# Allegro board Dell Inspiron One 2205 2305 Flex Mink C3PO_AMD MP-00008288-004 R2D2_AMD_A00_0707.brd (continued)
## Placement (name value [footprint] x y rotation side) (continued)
CN28  HEADER1X6PK6  [DH5_200P1X6_K6]  55.43 69.57 90 top
CN29  HEADER3PK3  [DH2_200P1X3_K3]  59.95 30.73 270 top
CN30  HEADER6PK5  [DH5_200P1X6_K5]  75.45 40.51 0 top
CN31  WFR8P  [DBH8_200P2X4_1000X505N]  167.65 62.61 270 top
CN32  WFR1X4P  [DBH4_200P1X4_1000X450]  172.73 62.61 270 top
CN33  WFR1X4P  [DWAF4_254P575W1006L]  169.43 241.55 0 top
CN34  WFR1X4P  [DCON_FAN_4_KORTAK]  180.86 241.17 0 top
CN35  WFR1X4P  [DCON_FAN_4_KORTAK]  190 242.44 90 top
D1  BAT54HT1G  [SOD323]  184.29 249.56 90 top
D2  BAT54HT1G  [SOD323]  188.35 252.22 0 top
D3  BAT54HT1G  [SOD323]  167.02 248.79 0 top
D4  BAT54HT1G  [SOD323]  142.76 220.6 90 top
D5  BAT54HT1G  [SOD323]  114.06 212.85 90 top
D6  BAT54HT1G  [SOD323]  93.36 207.9 0 top
D7  BAT54HT1G  [SOD323]  34.62 104.97 0 top
D8  BAT54C  [SOT23_3P_AKA]  140.85 87.25 180 top
D9  BAT54HT1G  [SOD323]  133.23 91.57 90 top
D10  BAT54C  [SOT23_3P_AKA]  158.51 77.34 270 top
D11  BAT54C  [SOT23_3P_AKA]  164.35 76.58 270 top
D12  BAT54C  [SOT23_3P_AKA]  180.1 64.14 180 top
D13  1SMA18A  [SMA]  137.81 13.46 180 top
D14  AOZ8212  [SOT23_3P]  13.85 65.28 90 bottom
D15  AOZ8212  [SOT23_3P]  13.85 49.28 90 bottom
D16  AOZ8212  [SOT23_3P]  109.38 14.3 270 bottom
D17  CPDU5V0U  [D0603_AC]  179.46 63.37 270 bottom
D18  CPDU12V0U  [D0603_AC]  147.2 57.78 180 top
EC1  220UF  [SEC630D600H]  22.11 114.3 90 top
EC2  470UF  [DEC063D110H]  60.08 47.05 270 top
EC11  100UF  [TC734331D]  150.25 61.21 180 top
F2  RESETTABLE1A5  [SF1206]  74.94 12.57 270 top
F3  RESETTABLE1A5  [SF1206]  46.49 10.41 0 top
F4  RESETTABLE1A5  [SF1206]  13.73 71.75 90 bottom
H1  OTHER_FMARK  [FM_A]  13.73 251.08 0 top
H2  OTHER_FMARK  [FM_A]  191.78 250.19 0 top
H3  OTHER_FMARK  [FM_A]  189.75 4.32 0 top
H4  OTHER_FMARK  [FM_A]  13.73 251.08 180 bottom
H5  OTHER_FMARK  [FM_A]  191.78 250.19 180 bottom
H6  OTHER_FMARK  [FM_A]  189.75 4.32 180 bottom
J1  DIMM240P  [SLT_DDR3-240_LOTES_WHT]  172.76 219.61 270 top
J2  DIMM240P  [SLT_DDR3-240_LOTES_WHT]  181.76 219.61 270 top
J3  HEADER2X13PK25  [SCON_HAD-VERTICAL_25P_K25]  125.36 84.58 180 top
J4  B2B-2X3P  [DH6_200P2X3N]  141.74 80.01 0 top
J6  B2B2X5K10  [DH9_254P2X5N_K10]  153.65 3.05 0 top
L1  80R  [L0805]  100.94 228.85 0 top
L2  30R  [L0603]  138.57 230.89 0 top
L3  80R  [L0805]  128.53 223.39 0 top
L4  150NH  [CKS750L700W520H]  109.48 217.81 90 top
L5  1UH  [CKS1150L1000W500H]  120.66 207.9 270 top
L6  0.36UH  [CKS1000L1000W400H]  104.02 183.64 270 top
L8  220R  [L0402]  63.64 170.69 0 top
L9  220R  [L0402]  57.92 170.18 270 top
L10  0.36UH  [CKS1000L1000W400H]  91.26 183.45 270 top
L11  220R  [L0603]  66.18 170.69 0 top
L13  220R  [L0402]  60.77 169.14 0 top
L14  100R  [L0603]  16.2 130.62 0 top
L15  220R  [L0603]  59.42 127.56 0 top
L16  600R  [L0603]  20 125.13 90 top
L17  600R  [L0603]  38.05 102.3 180 top
L18  600R  [L0603]  40.65 97.35 270 top
L19  600R  [L0603]  32.84 96.84 0 top
L20  60R  [L1806]  82.75 86.3 180 top
L21  60R  [L1806]  99.32 86.74 270 top
L22  60R  [L1806]  121.36 68.96 180 top
L23  220R  [L0603]  75.58 73.66 0 top
L24  220R  [L0603]  74.94 60.96 0 top
L25  70R  [L0402]  27.06 58.1 0 top
L26  30R  [L0603]  30.36 58.04 0 top
L27  30R  [L0603]  19.7 56.07 0 top
L28  120R  [L1206]  183.78 47.37 0 top
L29  30R  [L0603]  27.7 55.12 0 top
L30  30R  [L0603]  21.22 45.21 0 top
L31  70R  [L0402]  27.7 46.86 0 top
L32  70R  [L0402]  23.44 27.43 270 top
L33  60R  [L0805]  64.65 24.51 90 top
L34  120R  [L0805]  159.27 11.43 180 top
L35  70R  [L0402]  20.08 16.38 270 top
L36  90R  [CMC-2012_CHILISIN]  60.34 18.03 90 top
L37  90R  [CMC-2012_CHILISIN]  63.38 18.03 90 top
L38  90R  [CMC-2012_CHILISIN]  85.35 18.03 90 top
L39  90R  [CMC-2012_CHILISIN]  88.47 18.03 90 top
L40  30R  [L0603]  74.43 9.02 270 top
L41  120R  [L0805]  159.27 13.53 180 top
L42  30R  [L0603]  48.52 8 0 top
L43  220R  [L0402]  66.3 172.97 270 bottom
L44  220R  [L0402]  62.49 172.97 270 bottom
L45  220R  [L0402]  61.48 172.97 270 bottom
L46  220R  [L0402]  54.21 164.74 270 bottom
L47  30R  [L0603]  15 74.93 0 bottom
L50  600R  [L0603]  36.4 108.78 270 bottom
L51  90R  [CMC-2012_CHILISIN]  19.81 94.09 0 bottom
L52  90R  [CMC-2012_CHILISIN]  18.55 88.19 270 bottom
L53  220R  [L0402]  91.32 84.45 270 bottom
L55  220R  [L0402]  96.91 78.89 270 bottom
L56  220R  [L0402]  95.9 78.93 90 bottom
L57  220R  [L0402]  104.02 78.55 90 bottom
L58  220R  [L0603]  85.61 73.28 180 bottom
L59  220R  [L0402]  17.41 66.42 90 bottom
L60  70R  [L0402]  11.44 72.64 90 bottom
L61  220R  [L0402]  13.85 61.98 180 bottom
L62  220R  [L0402]  110.31 62.87 90 bottom
L63  220R  [L0402]  13.98 52.2 270 bottom
L64  220R  [L0402]  77.61 54.86 0 bottom
L65  220R  [L0402]  14.11 46.48 90 bottom
L66  2.2UH  [CKS290L250W210H]  133.49 38.23 0 bottom
L67  120R  [L0603]  15.38 39.05 270 bottom
L68  120R  [L0603]  124.85 40.01 0 bottom
L69  600R  [L0603]  54.85 37.08 270 bottom
L70  600R  [L0603]  52.84 31.11 90 bottom
L71  600R  [L0603]  147.01 21.02 270 bottom
L72  600R  [L0603]  145.43 20.76 270 bottom
L73  600R  [L0603]  143.9 20.76 270 bottom
L74  220R  [L0402]  106.49 15.21 0 bottom
L75  600R  [L0603]  141.49 19.18 90 bottom
L76  600R  [L0603]  139.96 19.18 90 bottom
L77  600R  [L0603]  138.44 19.18 90 bottom
L78  600R  [L0603]  136.92 19.18 90 bottom
L79  600R  [L0603]  135.39 18.92 90 bottom
L80  220R  [L0402]  106.49 13.39 0 bottom
L82  80R  [L0805]  179.34 66.78 0 bottom
LED1  LED_GRN  [LED0603_BRIGHT]  18.68 136.78 90 top
LED2  LED_YEL  [LED0603]  44.84 51.18 180 top
LED3  LED_WHT  [LED2_254P460L880W074H]  8.15 26.72 90 bottom
M1  OTHER_STANDOFF  [OTHER_SMT213]  154.02 185.1 0 top
M2  OTHER_STANDOFF  [OTHER_SMT213]  66.94 177.8 0 top
M3  OTHER_STANDOFF  [OTHER_SMT213]  66.94 126.36 0 top
M4  OTHER_STANDOFF  [OTHER_SMT213]  87.98 119.06 0 top
M5  OTHER_INSERT  [HOLE_STEEL-INSERT]  25.97 107.17 0 top
M6  OTHER_INSERT  [HOLE_STEEL-INSERT]  50.17 107.17 0 top
M7  OTHER_INSERT  [HOLE_STEEL-INSERT]  24.42 66.2 0 top
M8  OTHER_INSERT  [HOLE_STEEL-INSERT]  48.62 66.2 0 top
MH1  OTHER_M-HOLE  [HOLE_3-7_8MM_BOT14]  177.55 249 0 top
MH2  OTHER_M-HOLE  [HOLE_3-7_8MM_BOT14]  31.8 249 0 top
MH3  OTHER_M-HOLE  [HOLE_4-1_8MM_BOT14]  106.25 249 0 top
MH4  OTHER_M-HOLE  [HOLE_3-7_8MM_BOT14]  158.18 244.01 0 top
MH5  OTHER_M-HOLE  [HOLE_3-7_8MM_BOT14]  102 206.91 0 top
MH6  OTHER_M-HOLE  [HOLE_3-7_8MM_BOT14]  31.8 72.32 0 top
MH7  OTHER_M-HOLE  [HOLE_3-7_8MM_BOT14]  177.55 72.32 0 top
MH8  OTHER_M-HOLE  [HOLE_4-1_8MM_BOT14]  106.25 23.7 0 top
MH9  OTHER_M-HOLE  [HOLE_3-7_8MM_BOT14]  31.8 4 0 top
MH10  OTHER_M-HOLE  [HOLE_3-7_8MM_BOT14]  177.55 4 0 top
NOREF  -  [unnamed]  85.2 122.94 0 top
NOREF#2  -  [unnamed]  112.91 47.62 0 top
NOREF#3  -  [#2]  0.9 -20.32 0 top
NOREF#4  -  [unnamed]  45.86 136.4 0 top
NOREF#5  -  [unnamed]  72.27 83.12 0 top
NOREF#6  -  [unnamed]  76.34 167.13 0 top
NOREF#7  -  [unnamed]  134.44 214.44 0 top
NOREF#8  -  [#2]  65.73 240.92 180 bottom
PC1  4.7UF  [C0805]  107.96 243.14 180 top
PC2  150PF  [C0603]  126.1 237.4 90 top
PC3  10PF  [C0402]  154.32 237.49 0 top
PC4  1500PF  [C0603]  107.78 236.62 180 top
PC5  100PF  [C0402]  149.58 232.28 90 top
PC6  10UF  [C0805]  160.03 235.97 0 top
PC7  0.1UF  [C0402]  115.9 245.36 270 top
PC8  2200PF  [C0603]  128.59 238.37 180 top
PC9  0.1UF  [C0402]  119.76 245.25 270 top
PC10  2200PF  [C0603]  106.76 238.96 90 top
PC11  100PF  [C0603]  108.54 238.96 90 top
PC12  10UF  [C0805]  160.03 233.93 0 top
PC13  10UF  [C0805]  160.03 231.65 0 top
PC14  0.22UF  [C0603]  117.76 230.73 180 top
PC15  0.22UF  [C0603]  114.93 230.72 180 top
PC16  0.1UF  [C0603]  107.88 227.34 180 top
PC17  10UF  [C1206]  96.53 229.62 180 top
PC18  0.033UF  [C0603]  152.92 235.46 270 top
PC19  0.1UF  [C0603]  160.03 229.62 0 top
PC20  0.1UF  [C0603]  96.15 225.43 180 top
PC21  10UF  [C1206]  96.53 227.33 180 top
PC22  560UF  [DEC063D60H]  189.24 222.76 270 top
PC23  10UF  [C1206]  123.33 224.92 180 top
PC24  1UF  [C0603]  138.38 225.55 0 top
PC25  0.1UF  [C0603]  170.33 231.26 270 top
PC26  0.22UF  [C0603]  122.81 230.01 270 top
PC27  0.1UF  [C0603]  122.76 222.69 180 top
PC28  22UF  [C1210]  165.24 231.27 270 top
PC29  10UF  [C1206]  168.17 231.24 270 top
PC30  1UF  [C0603]  154.57 221.74 180 top
PC31  1UF  [C0603]  145.27 221.89 0 top
PC32  560UF  [DEC063D60H]  189.24 216.28 270 top
PC33  1UF  [C0603]  153.55 224.16 270 top
PC34  1UF  [C0603]  114.69 216.03 0 top
PC35  1UF  [C0603]  108.66 208.91 90 top
PC36  1UF  [C0603]  84.72 208.89 90 top
PC37  1UF  [C0603]  94.5 209.8 0 top
PC38  10UF  [C1206]  92.72 201.23 180 top
PC39  10UF  [C1206]  106.18 200.53 180 top
PC40  1500PF  [C0603]  92.4 199.01 180 top
PC41  0.1UF  [C0603]  105.87 198.37 180 top
PC42  22UF  [C0805]  114.95 192.53 180 top
PC43  0.1UF  [C0603]  114.5 188.72 180 top
PC44  560UF  [DEC063D60H]  121.8 197.87 270 top
PC45  560UF  [DEC063D60H]  115.44 197.04 270 top
PC46  22UF  [C0805]  114.95 190.5 180 top
PC47  560UF  [DEC063D60H]  82.81 178.56 0 top
PC48  560UF  [DEC063D60H]  93.36 174.24 0 top
PC49  560UF  [DEC063D60H]  86.88 173.48 0 top
PC50  560UF  [DEC063D60H]  90.82 168.28 0 top
PC51  560UF  [DEC063D60H]  83.7 167.51 0 top
PC52  0.1UF  [C0603]  189.49 165.23 180 top
PC53  560UF  [DEC063D60H]  189.24 157.99 270 top
PC54  560UF  [DEC063D60H]  189.24 151.51 270 top
PC55  0.1UF  [C0603]  73.52 133.07 90 top
PC56  560UF  [DEC063D60H]  77.58 132.26 0 top
PC57  0.1UF  [C0603]  70.37 123.06 0 top
PC58  1500PF  [C0603]  80.17 115.8 180 top
PC59  10UF  [C1206]  77.23 102.87 180 top
PC60  0.1UF  [C0603]  86.98 109.04 180 top
PC61  560UF  [DEC063D60H]  60.84 119.38 270 top
PC62  10UF  [C1206]  78.37 105.16 180 top
PC63  0.1UF  [C0603]  96.86 110.39 0 top
PC64  33PF  [C0402]  104.4 108.97 0 top
PC65  22UF  [C1210]  85.84 113.13 270 top
PC66  22UF  [C1210]  89.34 113.08 270 top
PC67  33PF  [C0402]  92.29 107.26 0 top
PC68  0.1UF  [C0603]  96.2 103.68 180 top
PC69  0.1UF  [C0603]  85.61 102.36 180 top
PC70  0.1UF  [C0603]  27.89 61.72 90 top
PC71  22UF  [C1206]  134.88 53.59 90 top
PC72  22UF  [C1206]  137.55 53.59 90 top
PC73  330UF  [TC734328D]  173.24 49.28 0 top
PC74  330UF  [TC734328D]  158 48.01 180 top
PC75  0.1UF  [C0603]  185.94 38.48 90 top
PC76  10UF  [C1206]  147.46 41.4 270 top
PC77  10UF  [C1206]  149.74 41.4 270 top
PC78  330UF  [SEC630D580H]  171.71 37.85 0 top
PC79  0.1UF  [C0603]  145.48 36.2 270 top
PC80  2200PF  [C0603]  138.95 33.66 180 top
PC81  0.01UF  [C0603]  141.62 33.15 270 top
PC82  10UF  [C1206]  174.13 26.42 90 top
PC83  0.1UF  [C0603]  153.05 30.61 180 top
PC84  330UF  [SEC630D580H]  152.54 26.54 0 top
PC85  330UF  [SEC630D580H]  181.62 40.26 270 top
PC86  1500PF  [C0603]  174.25 29.72 180 top
PC87  330UF  [SEC630D580H]  152.54 34.67 0 top
PC88  22UF  [C1210]  171.21 32.51 180 top
PC89  1000PF  [C0603]  163.9 20.83 0 top
PC90  0.1UF  [C0603]  167.02 16.89 90 top
PC91  4.7UF  [C0603]  168.92 16.89 90 top
PC92  220UF  [TC734318D]  67.96 24.38 90 top
PC93  0.1UF  [C0402]  175.65 10.41 0 top
PC94  1500PF  [C0603]  186.19 13.59 0 top
PC95  0.1UF  [C0603]  170.7 16.76 270 top
PC96  10UF  [C1206]  178.83 17.14 270 top
PC97  22UF  [C1210]  175.78 17.02 270 top
PC98  0.1UF  [C0402]  163.97 7.56 180 top
PC99  1UF  [C0603]  165.94 5.59 270 top
PC100  1UF  [C0603]  167.52 5.59 270 top
PC101  1500PF  [C0603]  128.59 238.37 180 bottom
PC102  0.1UF  [C0603]  119.33 233.68 180 bottom
PC103  10UF  [C0805]  160.06 236.12 0 bottom
PC104  10UF  [C0805]  160.06 233.93 0 bottom
PC105  22UF  [C1210]  123.2 223.01 180 bottom
PC106  2200PF  [C0603]  173.11 227.58 180 bottom
PC107  4700PF  [C0603]  119.64 220.85 90 bottom
PC108  10UF  [C1206]  123.24 226.01 180 bottom
PC109  1500PF  [C0603]  174.51 231.14 270 bottom
PC110  22UF  [C1210]  123.2 219.46 180 bottom
PC111  10UF  [C1206]  172.35 231.14 270 bottom
PC112  22UF  [C1210]  169.3 231.14 270 bottom
PC113  1500PF  [C0603]  123.07 216.79 180 bottom
PC114  0.22UF  [C0603]  138.09 217.96 270 bottom
PC115  0.22UF  [C0603]  110.82 207.01 270 bottom
PC116  0.22UF  [C0603]  89.8 203.96 270 bottom
PC117  22UF  [C1210]  92.91 199.58 180 bottom
PC118  22UF  [C1210]  93.8 196.02 180 bottom
PC119  4700PF  [C0603]  90.12 196.53 90 bottom
PC120  4700PF  [C0603]  102.17 196.19 90 bottom
PC121  22UF  [C1210]  106.18 198.88 180 bottom
PC122  10UF  [C1206]  93.74 192.98 180 bottom
PC123  22UF  [C1210]  105.73 195.3 180 bottom
PC124  10UF  [C1206]  105.71 192.32 180 bottom
PC125  22UF  [C1206]  121.8 157.99 0 bottom
PC126  47UF  [C1206]  114.06 157.86 0 bottom
PC127  22UF  [C1206]  116.72 155.32 180 bottom
PC128  22UF  [C1206]  123.96 155.19 180 bottom
PC129  22UF  [C1206]  114.06 152.78 0 bottom
PC130  22UF  [C1206]  120.66 152.65 0 bottom
PC131  22UF  [C1206]  116.72 150.24 180 bottom
PC132  22UF  [C1206]  124.22 149.61 180 bottom
PC133  22UF  [C1206]  114.06 147.7 0 bottom
PC134  22UF  [C1206]  121.55 147.32 0 bottom
PC135  22UF  [C1206]  124.22 145.03 180 bottom
PC136  22UF  [C1206]  116.6 145.03 180 bottom
PC137  1000PF  [C0603]  77.63 119.23 180 bottom
PC138  0.1UF  [C0603]  83.2 105.28 0 bottom
PC139  0.1UF  [C0603]  80.25 116.13 180 bottom
PC140  1500PF  [C0603]  83.2 106.81 0 bottom
PC141  10UF  [C1206]  80.86 114.07 180 bottom
PC142  10UF  [C1206]  80.66 108.01 90 bottom
PC143  1000PF  [C0603]  72.65 106.05 270 top
PC144  330UF  [TC734328D]  30.24 65.28 0 bottom
PC145  0.01UF  [C0603]  142.63 41.02 180 bottom
PC146  10UF  [C1206]  174.13 26.42 90 bottom
PC147  0.1UF  [C0603]  174.25 29.72 180 bottom
PC148  0.1UF  [C0603]  186.19 18.16 0 bottom
PC149  10UF  [C1206]  186.19 13.72 0 bottom
PC150  4.7UF  [C0805]  186.07 16.13 0 bottom
PC151  22UF  [C1210]  182.13 14.48 270 bottom
PC152  0.1UF  [C0402]  175.14 11.56 270 bottom
PC153  1000PF  [C0603]  191.15 20.32 270 bottom
PC154  10UF  [C1206]  78.37 108.01 90 bottom
PC155  10UF  [C0805]  70.37 130.18 180 top
PC156  10UF  [C0805]  70.37 132.21 180 top
PC157  10UF  [C0805]  71.38 127.13 270 top
PC158  10UF  [C0805]  62.11 112.9 180 top
PC159  10UF  [C0805]  62.11 110.74 180 top
PC160  10UF  [C0805]  62.11 115.06 180 top
PD1  B340A  [SMA]  140.98 46.99 90 top
PL1  80R  [L0805]  168.67 235.71 90 top
PL2  1UH  [CKS1000L1000W400H]  184.54 231.27 0 top
PL3  1.5UH  [CKS686L647W500H]  76.92 125.55 180 top
PL4  1.5UH  [CKR905P1150L1150W1050H]  69.99 116.2 90 top
PL5  80R  [L0805]  81.42 102.49 0 top
PL6  80R  [L0805]  92.24 112.98 270 top
PL7  80R  [L0805]  131.71 52.2 180 top
PL8  60R  [L0805]  143.39 52.07 0 top
PL9  10UH  [CKS660L660W280H]  135.52 46.61 90 top
PL10  60R  [L0805]  148.85 46.23 270 top
PL11  1.5UH  [CKR900P1140L1140W820H]  181.87 30.35 180 top
PL12  80R  [L0805]  178.32 23.11 0 top
PL13  3.3UH  [CKS1100L1000W400H]  161.81 31.24 90 top
PL14  80R  [L0805]  178.32 20.95 0 top
PL15  80R  [L0805]  174.13 22.23 270 top
PQ1  BSC889N03LS G  [DFN5_127P610W110H]  174.76 234.19 90 top
PQ2  BSC883N03LS G  [DFN5_127P610W110H]  174.76 228.22 270 top
PQ3  BSC883N03LS G  [DFN5_127P610W110H]  119.2 218.44 180 top
PQ4  BSC889N03LS G  [DFN5_127P610W110H]  125.87 218.38 0 top
PQ5  BSC883N03LS G  [DFN5_127P610W110H]  89.04 194.37 180 top
PQ6  BSC883N03LS G  [DFN5_127P610W110H]  102.25 193.99 180 top
PQ7  BSC889N03LS G  [DFN5_127P610W110H]  95.39 194.37 0 top
PQ8  BSC889N03LS G  [DFN5_127P610W110H]  108.72 194.06 0 top
PQ9  FDMS9620S  [DFN10_127P600W080H]  79.54 119.35 90 top
PQ10  FDMC7692S  [DFN5_065P330W080H]  79.77 108.2 270 top
PQ11  FDMS9620S  [DFN10_127P600W080H]  170.19 26.67 0 top
PQ12  BSC889N03LS G  [DFN5_127P610W110H]  183.27 17.91 180 top
PQ13  BSC883N03LS G  [DFN5_127P610W110H]  189.24 17.91 0 top
PQ14  FDMC7672S  [DFN5_065P330W080H]  81.42 111.63 90 top
PQ15  FDMC7672S  [DFN5_065P330W080H]  77.73 112.52 180 top
PR1  100K  [R0402]  105.55 241.71 270 top
PR2  9K76  [R0603]  148.02 232.54 90 top
PR3  0R  [R0402]  120.91 245.24 270 top
PR4  0R  [R0402]  122.18 245.24 270 top
PR5  4R7  [R0603]  107.93 241.36 0 top
PR6  4K7  [R0603]  105.09 238.9 90 top
PR7  26K1  [R0402]  119.96 229.91 90 top
PR8  3K24  [R0603]  128.59 236.64 0 top
PR9  100K  [R0402]  128.59 239.84 180 top
PR10  0R OHM  [R0402]  126.27 232.11 0 top
PR11  11K8  [R0402]  147.97 230.5 0 top
PR12  1K  [R0402]  105.75 235.09 90 top
PR13  95K3  [R0402]  107.87 230.05 180 top
PR14  11K8  [R0402]  147.97 229.36 0 top
PR15  100R  [R0402]  108.39 231.72 270 top
PR16  2K2  [R0402]  107.87 228.78 180 top
PR17  0R  [R0402]  126.28 235.47 180 top
PR18  75R  [R0603]  107.78 234.89 0 top
PR19  10R  [R0603]  151.9 224.16 90 top
PR20  4K7  [R0402]  150.38 224.28 90 top
PR21  619K  [R0402]  147.97 226.82 0 top
PR22  0R  [R0402]  107.88 233.45 0 top
PR23  100R  [R0603]  154.7 235.46 270 top
PR24  0R  [R0805]  159.9 227.71 0 top
PR25  100R  [R0402]  125.82 233.83 270 top
PR26  0R  [R0805]  159.9 225.43 180 top
PR27  10K  [R0603]  146.28 232.54 270 top
PR28  2R2  [R0805]  141.36 225.55 0 top
PR29  1UF  [C0402]  147.97 228.09 180 top
PR30  2R2  [R0603]  143.33 223.46 180 top
PR31  3K74  [R0402]  121.28 229.91 270 top
PR32  3K74  [R0603]  124.8 230.02 270 top
PR33  100R  [R0603]  107.88 225.62 0 top
PR34  1K8  [R0402]  117.05 228.41 270 top
PR35  1K8  [R0402]  114.38 228.37 270 top
PR36  0R  [R0805]  134.19 218.44 180 top
PR37  5K9  [R0603]  155.33 224.16 270 top
PR38  2R2  [R0805]  108.85 211.71 180 top
PR39  100K  [R0603]  100.59 110.36 180 top
PR40  10K  [R0603]  76.85 108.08 90 top
PR41  7K68  [R0603]  104.53 107.44 180 top
PR42  10K5  [R0603]  92.29 105.71 180 top
PR43  13K3  [R0402]  102.63 110.36 90 top
PR44  0R  [R0805]  95.59 105.69 180 top
PR45  0R  [R0805]  83.64 106.24 90 top
PR46  200K  [R0603]  92.34 108.81 0 top
PR47  93K1  [R0603]  104.53 105.66 0 top
PR48  147K  [R0603]  92.26 103.94 0 top
PR49  121K  [R0603]  137.55 35.43 180 top
PR50  10K  [R0603]  136.66 33.02 90 top
PR51  200K  [R0603]  143.65 33.66 0 top
PR52  71K5  [R0603]  138.95 32.13 0 top
PR53  0R  [R0805]  172.73 16.76 90 top
PR54  2R2  [R1206]  164.86 22.73 180 top
PR55  0R  [R0805]  175.27 13.21 180 top
PR56  0R  [R0805]  163.14 12.06 90 top
PR57  332K  [R0603]  163.02 9.14 180 top
PR58  154K  [R0603]  175.4 9.02 0 top
PR59  0R  [R0805]  164.98 15.11 270 top
PR60  10K  [R0402]  175.78 11.56 180 top
PR61  82K  [R0402]  166.25 3.56 0 top
PR62  390K  [R0402]  168.41 3.56 0 top
PR63  1K  [R0402]  125.83 237.25 180 bottom
PR64  14K  [R0603]  111.86 238.4 270 bottom
PR65  100R  [R0402]  126.27 235.48 180 bottom
PR66  75R  [R0603]  128.59 236.64 0 bottom
PR67  100R  [R0402]  107.86 233.45 0 bottom
PR68  2R2  [R1206]  176.92 227.2 180 bottom
PR69  10K  [R0603]  122.45 238.37 270 bottom
PR70  100K  [R0603]  117.78 230.73 0 bottom
PR71  100K  [R0603]  114.93 230.72 0 bottom
PR72  10K  [R0603]  177.68 235.46 270 bottom
PR73  0R  [R0402]  126.27 232.11 0 bottom
PR74  0R  [R0402]  107.88 230.05 180 bottom
PR75  0R  [R0402]  107.87 228.78 180 bottom
PR76  11K  [R0402]  120.57 229.9 270 bottom
PR77  0R  [R0805]  139.01 220.47 180 bottom
PR78  2R2  [R0805]  118.63 217.74 270 bottom
PR79  10K  [R0603]  80.53 119.25 180 bottom
PR80  2R2  [R1206]  78.47 122.38 270 bottom
PR81  2R2  [R1206]  74.69 107.95 270 top
PR82  13K3  [R0402]  92.29 107.26 0 bottom
PR83  0R  [R0805]  96.28 105.28 0 bottom
PR84  0R  [R0805]  85.74 104.39 90 bottom
PR85  10K  [R0402]  172.1 10.79 90 bottom
PR86  2R2  [R1206]  188.22 20.32 0 bottom
PR87  1UF  [C0402]  144.85 231.14 90 top
PU1  NCP5359A  [SO8_127P400W175H]  137.81 221.93 90 top
PU2  NCP5393BMNR2G  [QFN48_700L700W100HG]  117.63 237.28 270 top
PU3  RT8207A  [TQFN24_410L410W080HG]  153.81 230.25 180 top
PU4  NCP5359A  [SO8_127P400W175H]  88.33 206.88 180 top
PU5  NCP5359A  [SO8_127P400W175H]  112.28 206.88 180 top
PU6  TPS51218  [SON10_050P315W100H]  100.19 107.14 90 top
PU7  TPS51218  [SON10_050P315W100H]  88.15 105.92 90 top
PU8  RT8272  [SOP8_127P394W168HG]  141.87 38.23 180 top
PU9  RT8206B  [QFN32_510L510W093HG]  168.79 10.92 0 top
Q1  ME2N7002E  [SOT23_3P_GDS]  79.13 228.6 180 top
Q2  ME2N7002E  [SOT23_3P_GDS]  82.43 228.6 180 top
Q3  2N7002E  [SOT23_3P_GDS]  7.12 197.61 180 top
Q4  2N7002  [SOT23_3P_GDS]  12.2 192.41 180 top
Q5  2N7002  [SOT23_3P_GDS]  6.23 192.28 180 top
Q6  ME2306D-G  [SOT23_3P_GDS]  6.87 187.32 0 top
Q7  FDV301N  [SOT23_3P_GDS]  43.64 172.02 270 top
Q8  MMBT3904  [SOT23_3P_BCE]  189.37 141.6 270 top
Q9  MMBT3904  [SOT23_3P_BCE]  189.37 133.48 270 top
Q10  MMBT3904LT1G  [SOT23_3P_BCE]  105.29 111.76 180 top
Q11  MMBT3904LT1G  [SOT23_3P_BCE]  68.65 101.35 90 top
Q12  2N7002E  [SOT23_3P_GDS]  114.21 97.87 90 top
Q13  2N7002E  [SOT23_3P_GDS]  65.61 103.82 90 top
Q14  MMBT3904LT1G  [SOT23_3P_BCE]  106.94 99.82 0 top
Q15  2N7002E  [SOT23_3P_GDS]  97.93 100.2 270 top
Q16  MMBT3904LT1G  [SOT23_3P_BCE]  92.47 100.46 270 top
Q17  FDV301N  [SOT23_3P_GDS]  121.3 78.42 0 top
Q18  2N7002  [SOT23_3P_GDS]  158.51 73.15 270 top
Q19  2N7002  [SOT23_3P_GDS]  164.35 72.9 270 top
Q20  2N7002E  [SOT23_3P_GDS]  24.65 61.21 270 top
Q21  2N7002E  [SOT23_3P_GDS]  30.87 64.52 0 top
Q22  2N7002  [SOT23_3P_GDS]  179.97 58.04 0 top
Q23  2N7002E  [SOT23_3P_GDS]  166 48.77 90 top
Q24  2N7002E  [SOT23_3P_GDS]  68.21 50.29 270 top
Q25  2N7002E  [SOT23_3P_GDS]  179.59 50.55 180 top
Q26  SI4134DY  [SO8_127P400W175H]  128.03 48.13 270 top
Q27  PMBS3904  [SOT23_3P_BCE]  36.52 45.53 180 top
Q28  2N7002E  [SOT23_3P_GDS]  68.21 46.48 270 top
Q29  MMBT3904  [SOT23_3P_BCE]  107.2 44.45 180 top
Q30  SI4134DY  [SO8_127P400W175H]  162.06 41.91 180 top
Q31  SI4134DY  [SO8_127P400W175H]  173.75 44.07 270 top
Q32  MMBT3904LT1G  [SOT23_3P_BCE]  68.21 53.47 270 top
Q33  PMBS3904  [SOT23_3P_BCE]  35.44 42.04 270 top
Q34  BAT54A  [SOT23_3P_AKA]  17.66 47.75 0 top
Q35  MMBT3904LT1G  [SOT23_3P_BCE]  58.3 42.42 270 top
Q36  2N7002E  [SOT23_3P_GDS]  127.26 43.56 0 top
Q37  2N7002E  [SOT23_3P_GDS]  154.82 43.81 270 top
Q38  2N7002E  [SOT23_3P_GDS]  72.53 30.99 90 top
Q39  MMBT3904LT1G  [SOT23_3P_BCE]  75.78 28.88 90 top
Q40  2N7002  [SOT23_3P_GDS]  60.97 36.45 0 top
Q41  2N7002E  [SOT23_3P_GDS]  143.77 29.59 270 top
Q42  2N7002  [SOT23_3P_GDS]  26.17 33.4 90 top
Q43  2N7002  [SOT23_3P_GDS]  30.05 33.15 90 top
Q44  2N7002  [SOT23_3P_GDS]  15.89 27.56 270 top
Q45  PMBS3904  [SOT23_3P_BCE]  53.41 26.86 270 top
Q46  2N7002E  [SOT23_3P_GDS]  68.72 30.99 90 top
Q47  SI4134DY  [SO8_127P400W175H]  75.45 21.84 270 top
Q48  2N7002E  [SOT23_3P_GDS]  139.46 29.59 270 top
Q49  NUP4201MR6T1G  [SOT23_6P]  61.73 13.08 180 top
Q50  NUP4201MR6T1G  [SOT23_6P]  86.75 13.08 180 top
Q51  2N7002  [SOT23_3P_GDS]  98.18 117.09 0 bottom
Q53  MMBT3904LT1G  [SOT23_3P_BCE]  107.07 108.84 0 bottom
Q54  2N7002E  [SOT23_3P_GDS]  105.8 105.54 270 bottom
Q55  2N7002E  [SOT23_3P_GDS]  99.71 103.12 270 bottom
Q56  NTR4171P  [SOT23_3P_GDS]  76.67 89.42 270 bottom
Q57  2N7002E  [SOT23_3P_GDS]  80.66 89.41 270 bottom
Q58  NUP4201MR6T1G  [SOT23_6P]  15.89 91.76 90 bottom
Q59  NTMS4807N  [SO8_127P400W175H]  30.62 60.2 90 bottom
Q60  MMBT3904  [SOT23_3P_BCE]  168.92 53.21 180 bottom
Q61  2N7002E  [SOT23_3P_GDS]  176.29 50.55 0 bottom
Q62  2N7002E  [SOT23_3P_GDS]  179.59 50.55 180 bottom
Q63  NTR4171P  [SOT23_3P_GDS]  184.41 46.35 180 bottom
Q64  2N7002  [SOT23_3P_GDS]  187.34 43.43 180 bottom
Q65  2N7002  [SOT23_3P_GDS]  7.88 19.94 180 bottom
Q66  2N7002  [SOT23_3P_GDS]  13.73 4.32 180 bottom
Q67  NTR4171P  [SOT23_3P_GDS]  10.42 4.32 180 bottom
Q70  2N7002E  [SOT23_3P_GDS]  78.5 205.36 90 top
Q96  2N7002  [SOT23_3P_GDS]  13.03 177.29 90 top
Q608  FDV301N  [SOT23_3P_GDS]  101.55 117.03 0 bottom
Q609  ME2N7002KW  [SOT363_6P]  77.1 201.8 90 top
R1  4K7  [R0402]  187.21 248.92 90 top
R2  1K  [R0402]  188.86 249.56 0 top
R3  4K7  [R0402]  166.51 246.38 90 top
R4  1K  [R0402]  169.05 246.38 90 top
R5  0R  [R0402]  118.49 245.31 90 top
R6  4K7  [R0402]  184.03 247.01 0 top
R7  10K  [R0402]  188.86 250.7 180 top
R8  1K  [R0402]  135.14 239.78 90 top
R9  150R  [R0402]  188.86 248.41 180 top
R10  10K  [R0402]  185.81 250.32 270 top
R11  1K  [R0402]  185.81 248.03 270 top
R12  10K  [R0402]  167.78 246.38 270 top
R13  150R  [R0402]  170.32 246.38 270 top
R14  10K  [R0402]  140.47 233.04 90 top
R15  150R  [R0402]  185.81 245.75 270 top
R16  1K  [R0402]  114.32 245.36 270 top
R17  0R  [R0402]  117.22 245.31 270 top
R18  27R  [R0402]  126.1 240.91 180 top
R19  6K8  [R0402]  81.42 233.17 180 top
R20  300R  [R0402]  126.1 239.64 180 top
R21  1K  [R0402]  128.41 241.68 270 top
R22  8K2  [R0402]  78.75 231.52 180 top
R23  6K8  [R0402]  83.58 232.79 270 top
R24  0R  [R0402]  133.87 239.78 270 top
R25  21K5  [R0603]  138.5 232.54 180 top
R26  0R  [R0402]  82.31 231.52 270 top
R27  1K  [R0603]  112.02 227.83 180 top
R28  0R  [R0402]  80.91 231.52 90 top
R29  0R  [R0402]  113.05 229.81 90 top
R30  4K22  [R0402]  81.66 225.43 270 top
R31  0R  [R0402]  82.65 225.43 270 top
R32  0R  [R0402]  83.67 225.43 270 top
R33  0R  [R0402]  84.69 225.43 270 top
R34  100K  [R0402]  85.7 225.43 270 top
R35  100K  [R0402]  86.72 225.43 270 top
R36  4K22  [R0402]  32.06 225.17 270 top
R37  4K22  [R0402]  33.2 225.17 270 top
R38  15R  [R0603]  164.73 217.93 90 top
R39  0R  [R0402]  79.39 225.43 90 top
R40  0R  [R0402]  80.53 225.43 90 top
R41  100K  [R0402]  87.73 225.43 90 top
R42  8K2  [R0402]  19.03 225.81 0 top
R43  10K  [R0603]  112.02 226 0 top
R44  15R  [R0603]  166.25 215.14 90 top
R45  0R  [R0603]  118.51 228.16 270 top
R46  0R  [R0603]  115.72 228.12 270 top
R47  0R  [R0603]  114.56 225.43 270 top
R48  0R  [R0603]  117.09 225.42 270 top
R49  8K2  [R0402]  78.5 209.3 90 top
R50  100K  [R0402]  81.04 209.3 90 top
R51  0R  [R0402]  83.2 209.17 90 top
R52  2R2  [R0805]  88.02 211.84 180 top
R53  2R2  [R0603]  91.07 211.58 180 top
R54  2R2  [R0603]  111.52 212.22 270 top
R55  15R  [R0603]  166.25 217.93 270 top
R56  1K  [R0402]  26.14 209.55 270 top
R57  0R  [R0402]  27.16 209.55 270 top
R58  0R  [R0402]  48.8 209.55 270 top
R59  4K7  [R0402]  49.79 209.55 270 top
R60  4K7  [R0402]  51.18 209.52 270 top
R61  0R  [R0402]  39.05 208.53 270 top
R62  0R  [R0402]  40.57 208.53 270 top
R63  0R  [R0402]  42.09 208.53 270 top
R64  0R  [R0402]  43.62 208.53 270 top
R65  0R  [R0402]  45.14 208.53 270 top
R66  1K  [R0402]  14.7 207.67 270 top
R67  1K  [R0402]  15.72 207.67 270 top
R68  15R  [R0603]  164.73 215.14 270 top
R69  8K2  [R0402]  79.77 209.3 90 top
R70  150R  [R0402]  39.05 206.38 270 top
R71  150R  [R0402]  40.57 206.38 270 top
R72  150R  [R0402]  42.09 206.38 270 top
R73  0R  [R0402]  44.59 206.25 180 top
R74  10K  [R0402]  99.58 120.14 0 bottom
R75  0R  [R0402]  56.02 195.33 90 top
R76  0R  [R0402]  57.03 195.33 90 top
R77  0R  [R0402]  58.05 195.33 90 top
R78  0R  [R0402]  59.07 195.33 90 top
R79  0R  [R0402]  60.21 195.33 90 top
R80  0R  [R0402]  61.22 195.33 90 top
R81  0R  [R0402]  62.24 195.33 90 top
R82  0R  [R0402]  63.51 195.33 90 top
R83  0R  [R0402]  64.65 195.33 90 top
R84  2R2  [R0805]  113.4 201.5 180 top
R85  0R  [R0805]  30.11 200.66 180 top
R86  2R2  [R0805]  92.29 203.91 0 top
R87  0R  [R0603]  29.35 198.12 270 top
R88  21K5  [R0402]  6.61 194.82 180 top
R89  0R  [R0402]  52.97 195.33 270 top
R90  75R  [R0402]  7.5 202.95 270 top
R91  0R  [R0402]  8.52 202.95 270 top
R92  75R  [R0402]  9.54 202.95 270 top
R93  0R  [R0402]  10.55 202.95 270 top
R94  75R  [R0402]  11.57 202.95 270 top
R95  0R  [R0402]  12.58 202.95 270 top
R96  0R  [R0402]  13.6 202.95 270 top
R97  0R  [R0402]  14.62 202.95 270 top
R98  0R  [R0603]  73.23 195.26 0 top
R99  100K  [R0402]  8.65 193.42 270 top
R100  100K  [R0402]  9.79 193.42 270 top
R101  0R  [R0402]  64.78 184.28 180 top
R102  0R  [R0402]  64.78 185.29 180 top
R103  15R  [R0402]  114.77 183.97 90 top
R104  0R  [R0805]  66.37 196.09 270 top
R105  0R  [R0402]  53.99 195.33 270 top
R106  0R  [R0402]  55 195.33 270 top
R107  120K  [R0402]  9.15 190.75 0 top
R108  0R  [R0805]  12.46 184.91 270 top
R109  330R  [R0805]  11.95 188.47 90 top
R110  511R  [R0402]  110.63 183.54 270 top
R111  511R  [R0402]  111.64 183.54 270 top
R112  0R  [R0402]  62.37 184.91 90 top
R113  0R  [R0402]  67.07 185.29 180 top
R114  169R  [R0402]  111.01 177.75 180 top
R115  0R  [R0402]  61.1 184.91 90 top
R116  3K  [R0402]  60.34 172.59 90 top
R117  2K2  [R0402]  49.29 176.91 270 top
R118  20K  [R0402]  42.05 174.75 270 top
R119  20K  [R0402]  44.08 174.75 270 top
R120  0R  [R0402]  45.86 174.75 270 top
R121  4K7  [R0402]  53.48 168.28 90 top
R122  4K7  [R0402]  48.52 172.59 270 top
R123  0R  [R0402]  49.54 172.59 270 top
R124  0R  [R0402]  46.87 174.75 90 top
R125  4K7  [R0402]  59.07 172.47 90 top
R126  0R  [R0402]  59.07 168.15 270 top
R127  3K  [R0402]  54.62 167.89 270 top
R128  3K  [R0402]  55.76 167.89 270 top
R129  3K  [R0402]  54.62 170.31 90 top
R130  3K  [R0402]  55.76 170.31 90 top
R131  0R  [R0402]  59.07 170.18 90 top
R132  1K  [R0402]  59.07 166.12 270 top
R133  0R  [R0402]  51.57 167.64 0 top
R134  0R  [R0402]  51.57 166.24 0 top
R135  1K8  [R0402]  65.9 166.17 0 top
R136  0R  [R0402]  18.55 163.58 90 top
R137  4K7  [R0402]  52 165.13 0 top
R138  301R  [R0402]  77.86 164.72 0 top
R139  4K7  [R0402]  46.85 164.44 0 top
R140  4K7  [R0402]  52 164.03 0 top
R141  4K7  [R0402]  46.85 163.42 0 top
R142  301R  [R0402]  77.86 163.32 0 top
R143  0R  [R0402]  51.95 163.07 0 top
R144  150R  [R0402]  44.36 162.23 0 top
R145  1K  [R0402]  157.44 149.05 45 top
R146  15R  [R0603]  188.35 144.65 90 top
R147  10K  [R0402]  26.3 147.07 180 top
R148  1K  [R0402]  22.36 146.56 180 top
R149  0R  [R0402]  21.6 148.34 270 top
R150  12K7  [R0603]  27.57 145.54 180 top
R151  2K2  [R0402]  186.95 140.59 90 top
R152  0R  [R0402]  33.64 143.57 180 top
R153  49R9  [R0402]  44.33 142.98 180 top
R154  0R  [R0402]  33.64 142.56 180 top
R155  49R9  [R0402]  44.35 141.5 180 top
R156  0R  [R0402]  33.67 141.41 180 top
R157  15R  [R0603]  188.35 136.53 90 top
R158  0R  [R0402]  33.67 140.14 180 top
R159  2K2  [R0402]  189.62 139.32 0 top
R160  0R  [R0402]  33.67 139.13 180 top
R161  0R  [R0603]  23.12 136.27 180 top
R162  40R2  [R0402]  60.46 132.69 90 top
R163  2K2  [R0402]  186.95 132.08 90 top
R164  0R  [R0402]  33.67 134.68 0 top
R165  120R  [R0402]  20.26 136.69 270 top
R166  0R  [R0402]  16.19 134.28 0 top
R167  15R  [R0603]  189.88 144.65 270 top
R168  0R  [R0402]  33.67 133.67 0 top
R169  0R  [R0402]  12.52 133.41 0 top
R170  330R  [R0402]  16.2 133.03 0 top
R171  0R  [R0402]  33.67 132.46 0 top
R172  0R  [R0402]  33.67 138.11 0 top
R173  0R  [R0402]  33.67 131.25 0 top
R174  0R  [R0402]  33.67 137.1 0 top
R175  0R  [R0402]  36.46 132.46 270 top
R176  0R  [R0402]  35.82 129.41 0 top
R177  10K  [R0603]  12.58 131.95 0 top
R178  40R2  [R0603]  61.92 132.78 90 top
R179  15R  [R0603]  189.88 136.53 270 top
R180  1K  [R0402]  100.34 120.78 90 top
R181  0R  [R0402]  97.17 120.52 90 top
R182  10K  [R0402]  99.2 120.52 90 top
R183  1K  [R0402]  102.88 120.52 90 top
R184  39R2  [R0402]  109.23 120.52 90 top
R185  39R2  [R0402]  110.25 120.52 90 top
R186  0R  [R0402]  33.67 129.03 0 top
R187  2K  [R0402]  55.03 132.08 270 top
R188  1K27  [R0402]  56.04 132.08 270 top
R189  0R  [R0402]  57.24 132.05 270 top
R190  0R  [R0402]  58.46 132.05 270 top
R191  0R  [R0603]  27.44 132.21 270 top
R192  0R  [R0402]  33.67 127.83 0 top
R193  1K  [R0402]  100.37 117.65 90 top
R194  2K2  [R0402]  189.32 130.81 270 top
R195  4K7  [R0402]  25.08 127.29 0 top
R196  0R  [R0603]  61.61 125.48 90 top
R197  0R  [R0402]  33.67 126.62 0 top
R198  4K7  [R0402]  25.08 126.15 0 top
R199  51K  [R0402]  34.81 119.38 180 top
R200  0R  [R0402]  33.67 125.41 0 top
R201  300R  [R0402]  102.37 117.98 0 top
R202  0R  [R0402]  33.67 124.4 0 top
R203  0R  [R0402]  33.67 123.19 0 top
R204  0R  [R0402]  101.36 115.82 180 top
R205  0R  [R0402]  101.36 114.81 180 top
R206  44R2  [R0402]  101.74 120.52 270 top
R207  0R  [R0402]  104.66 120.52 270 top
R208  300R  [R0402]  106.89 120.52 270 top
R209  0R  [R0603]  49.48 195.45 270 top
R210  0R  [R0402]  113.93 118.62 270 top
R211  0R  [R0402]  114.95 118.62 270 top
R213  4K75  [R0402]  109.87 108.33 180 top
R214  300R  [R0402]  106.72 117.65 270 top
R215  301R  [R0402]  107.99 117.65 270 top
R216  10K  [R0402]  107.91 108.81 90 top
R217  1K  [R0402]  101.48 104.14 180 top
R218  10K  [R0402]  95.01 99.57 90 top
R219  20K5  [R0402]  104.66 99.57 90 top
R220  20K5  [R0402]  110.12 111.76 270 top
R221  10K  [R0402]  105.42 101.35 0 top
R222  0R  [R0402]  75.58 100.58 0 top
R223  1K  [R0402]  66.24 99.12 270 top
R224  20K5  [R0402]  66.5 96.46 90 top
R225  1K  [R0402]  37.29 104.33 90 top
R226  4K7  [R0402]  38.81 104.33 90 top
R227  0R  [R0805]  117.49 101.85 0 top
R228  8K2  [R0402]  64.46 99.06 270 top
R229  20K5  [R0402]  89.42 102.23 180 top
R230  10R  [R0402]  114.26 103.86 270 top
R231  10K  [R0402]  100.85 100.2 180 top
R232  10K  [R0402]  114.18 100.08 180 top
R233  0R  [R0603]  23.63 91.82 180 top
R234  0R  [R0603]  26.3 90.93 180 top
R235  0R  [R0805]  76.21 91.95 270 top
R236  0R  [R0805]  78.24 91.95 270 top
R237  1K  [R0402]  89.67 100.46 270 top
R238  10K  [R0402]  72.27 91.44 270 top
R239  0R  [R0402]  73.29 91.44 270 top
R240  300R  [R0402]  129.17 91.31 270 top
R241  0R  [R0402]  53.54 190.5 0 bottom
R242  0R  [R0402]  53.54 191.52 0 bottom
R243  0R  [R0402]  29.09 170.88 270 top
R244  4K7  [R0402]  134.88 92.08 90 top
R245  0R  [R0402]  29.03 168.59 270 top
R246  4K7  [R0402]  131.71 91.31 90 top
R247  0R  [R0603]  80.02 91.57 90 top
R248  4K7  [R0402]  37.6 112.46 180 top
R249  1K  [R0402]  141.87 90.17 90 top
R250  1M  [R0402]  92.69 84.04 180 top
R251  2K2  [R0402]  77.73 82.68 180 top
R252  10K  [R0402]  143.27 84.33 270 top
R253  4K7  [R0402]  39.63 112.46 0 top
R254  590R  [R0402]  108.72 82.36 270 top
R255  2K  [R0402]  109.74 82.36 270 top
R256  0R  [R0402]  44.97 76.45 90 top
R257  0R  [R0402]  46.11 76.45 90 top
R258  0R  [R0402]  82.81 203.58 90 top
R259  2K2  [R0402]  77.73 79.25 0 top
R260  1K  [R0402]  147.97 77.34 270 top
R261  0R  [R0402]  110.88 83.19 90 top
R262  10K  [R0402]  111.9 83.19 90 top
R263  0R  [R0402]  112.91 83.19 90 top
R264  2K2  [R0402]  74.81 78.11 0 top
R265  10K  [R0402]  85.35 83.06 90 top
R269  0R  [R0402]  119.01 78.23 270 top
R270  10K  [R0402]  110.88 80.64 90 top
R271  10K  [R0402]  111.9 80.64 90 top
R272  4K7  [R0402]  158.13 75.18 0 top
R273  2K2  [R0402]  77.73 81.53 180 top
R274  1K  [R0402]  146.7 77.34 270 top
R275  10K  [R0402]  77.73 80.39 180 top
R276  0R  [R0603]  73.04 75.69 180 top
R277  0R  [R0402]  155.97 74.55 270 top
R278  1K  [R0402]  72.02 69.09 90 top
R279  10K  [R0402]  77.73 78.11 180 top
R280  4K7  [R0402]  159.9 69.85 0 top
R281  0R  [R0402]  37.48 77.09 180 top
R282  4K7  [R0402]  163.71 69.6 0 top
R283  21K5  [R0603]  28.33 64.77 90 top
R284  8K2  [R0402]  119.64 72.64 90 top
R285  10K  [R0402]  114.95 72.52 90 top
R286  10K  [R0402]  53.73 72.71 90 top
R287  10K  [R0402]  151.9 67.56 180 top
R288  10M  [R0402]  117.23 67.18 180 top
R289  1K  [R0402]  19.59 63.25 90 top
R290  10K  [R0402]  151.9 66.42 180 top
R291  0R  [R0402]  167.14 75.95 270 top
R292  10K  [R0402]  152.03 69.85 90 top
R293  10K  [R0402]  153.17 69.85 90 top
R294  10K  [R0402]  151.9 65.28 180 top
R295  12K4  [R0402]  71.13 64.52 0 top
R296  10R  [R0402]  64.4 69.09 90 top
R297  4K7  [R0402]  178.38 60.64 180 top
R298  0R  [R0402]  159.9 70.99 180 top
R299  0R  [R0402]  163.71 70.74 180 top
R300  4K7  [R0402]  167.14 73.03 270 top
R301  0R  [R0402]  74.69 62.36 0 top
R302  4K7  [R0402]  155.97 71.37 270 top
R303  0R  [R0805]  52.46 64.01 0 top
R304  10K  [R0402]  150.89 69.85 270 top
R305  10K  [R0402]  154.32 69.85 270 top
R306  49K9  [R0402]  30.49 59.82 180 top
R307  100K  [R0603]  183.65 63.37 0 top
R308  0R  [R0603]  184.8 65.41 0 top
R309  0R  [R0402]  184.67 57.91 0 top
R310  10K  [R0402]  73.9 57.23 0 top
R311  4K99  [R0402]  68.84 64.52 180 top
R312  0R  [R0402]  183.14 56.64 0 top
R313  10K  [R0402]  73.9 56.21 0 top
R314  8K2  [R0402]  64.91 55.63 0 top
R315  10K  [R0402]  73.9 55.19 0 top
R316  1K  [R0402]  167.46 54.86 0 top
R317  100K  [R0402]  30.49 62.1 180 top
R318  10K  [R0402]  73.92 53.98 0 top
R319  200K  [R0402]  30.49 60.96 180 top
R320  0R  [R0603]  184.67 60.33 0 top
R321  10K  [R0402]  73.92 52.7 0 top
R322  8K2  [R0402]  70.85 52.37 0 top
R323  100K  [R0402]  32.14 61.47 270 top
R324  0R  [R0402]  73.9 58.37 180 top
R325  10K  [R0402]  97.86 48.01 90 top
R326  10K  [R0402]  88.95 47.97 90 top
R327  33R  [R0402]  94.5 47.88 90 top
R328  33R  [R0402]  95.51 47.88 90 top
R329  33R  [R0402]  96.53 47.88 90 top
R330  0R  [R0402]  180.1 61.09 270 top
R331  0R  [R0603]  19 53.85 180 top
R332  0R  [R0603]  30.24 52.07 270 top
R333  330R  [R0805]  174.64 53.85 0 top
R334  2K  [R0402]  41.67 50.8 270 top
R335  10K  [R0402]  71.51 56.52 180 top
R336  330R  [R0805]  166.25 52.07 180 top
R337  100K  [R0402]  178.7 45.34 90 top
R338  33R  [R0402]  90.43 45.21 90 top
R339  22R  [R0402]  93.48 45.21 90 top
R340  10K  [R0402]  94.5 45.21 90 top
R341  10K  [R0402]  97.74 45.21 90 top
R342  10K  [R0402]  98.75 45.21 90 top
R343  0R  [R0402]  182.26 58.42 270 top
R344  0R  [R0603]  184.54 55.12 0 top
R345  1K5  [R0402]  72.65 47.88 0 top
R346  0R  [R0603]  21.98 51.82 0 top
R347  0R  [R0603]  30.24 49.4 270 top
R348  100K  [R0402]  157.24 44.45 90 top
R349  20M  [R0402]  79.26 46.93 180 top
R350  2K2  [R0402]  110.37 49.4 270 top
R351  2K2  [R0402]  112.17 53.64 0 top
R352  5K1  [R0402]  21.79 53.09 0 top
R353  0R  [R0402]  112.16 52.01 0 top
R354  8K2  [R0402]  109.36 49.4 90 top
R355  4K7  [R0402]  180.99 54.74 270 top
R356  4K7  [R0603]  130.31 44.32 180 top
R357  100K  [R0603]  182.38 54.61 270 top
R358  0R  [R0402]  40.65 44.45 180 top
R359  4K7  [R0402]  39.76 40.89 90 top
R360  4K7  [R0402]  40.78 40.89 90 top
R361  10K  [R0402]  40.65 43.37 0 top
R362  39K2  [R0402]  34.3 45.59 270 top
R363  1K  [R0402]  42.81 43.69 180 top
R364  0R  [R0402]  85.1 40.13 90 top
R365  0R  [R0402]  86.37 40.13 90 top
R366  0R  [R0402]  87.64 40.13 90 top
R367  0R  [R0402]  89.42 40.13 90 top
R368  0R  [R0402]  45.98 44.83 270 top
R369  10K  [R0402]  45.98 47.12 90 top
R370  4K7  [R0402]  47 47.12 90 top
R371  4K7  [R0402]  48.02 47.12 90 top
R372  4K7  [R0402]  49.03 47.12 90 top
R373  4K7  [R0402]  50.49 47.12 90 top
R374  30K1  [R0402]  168.92 42.16 0 top
R375  2K2  [R0402]  106.69 41.78 0 top
R376  51K  [R0402]  31.89 43.43 270 top
R377  0R  [R0402]  32.9 43.43 270 top
R378  10K  [R0402]  42.3 47.12 0 top
R379  33R  [R0402]  92.97 42.42 270 top
R380  0R  [R0402]  47 44.83 90 top
R381  0R  [R0402]  48.02 44.83 90 top
R382  0R  [R0402]  49.03 44.83 90 top
R383  0R  [R0402]  50.05 44.83 90 top
R384  10K  [R0402]  51.06 44.83 90 top
R385  0R  [R0402]  55.26 40.01 180 top
R386  510R  [R0402]  75.32 49.78 270 top
R387  49K9  [R0402]  124.98 44.07 90 top
R388  0R  [R0402]  39.89 39.37 180 top
R389  4K7  [R0402]  110.63 41.02 270 top
R390  10K  [R0402]  101.64 38.38 0 top
R391  1K  [R0402]  42.81 44.83 0 top
R392  0R  [R0402]  39.89 38.35 180 top
R393  4K7  [R0402]  37.35 38.23 180 top
R394  0R  [R0402]  98.88 48.01 270 top
R395  33R  [R0402]  99.9 48.01 270 top
R396  22R  [R0402]  100.91 48.01 270 top
R397  22R  [R0402]  101.93 48.01 270 top
R398  22R  [R0402]  102.94 48.01 270 top
R399  22R  [R0402]  103.96 48.01 270 top
R400  22R  [R0402]  104.98 48.01 270 top
R401  0R  [R0402]  106.12 48.01 270 top
R402  2K2  [R0402]  107.26 48.01 270 top
R403  10K  [R0402]  90.12 47.95 270 top
R404  10K  [R0402]  83.07 47.88 270 top
R405  10K  [R0402]  85.48 47.88 270 top
R406  10K  [R0402]  91.45 47.88 270 top
R407  10K  [R0402]  92.47 47.88 270 top
R408  10K  [R0402]  93.48 47.88 270 top
R409  0R  [R0402]  55.26 37.97 180 top
R410  0R  [R0402]  63.76 37.72 180 top
R411  0R  [R0603]  16.58 37.66 90 top
R412  4K7  [R0402]  37.35 36.96 180 top
R413  0R  [R0402]  55.26 36.96 180 top
R414  0R  [R0402]  31.89 41.27 90 top
R415  10K  [R0402]  23.12 36.7 180 top
R416  4K7  [R0402]  29.67 35.94 270 top
R417  22R  [R0402]  112.66 41.02 90 top
R418  0R  [R0603]  25.73 36 180 top
R419  10K  [R0402]  55.26 35.94 180 top
R420  10K  [R0402]  89.8 35.43 0 top
R421  33R  [R0402]  96.66 40.26 90 top
R422  22K  [R0402]  85 45.27 270 top
R423  10K  [R0402]  88.36 45.27 270 top
R424  120K  [R0402]  80.66 200.41 180 top
R425  10K  [R0402]  101.61 45.21 270 top
R426  10K  [R0402]  102.75 45.21 270 top
R427  10K  [R0402]  103.77 45.21 270 top
R428  10K  [R0402]  104.79 45.21 270 top
R429  200K  [R0402]  166.51 42.16 180 top
R430  49K9  [R0402]  158.51 44.45 270 top
R431  4K7  [R0402]  40.78 34.54 180 top
R432  0R  [R0402]  35.32 38.61 90 top
R433  1K  [R0402]  89.8 33.53 0 top
R434  0R  [R0402]  57.92 40.26 0 top
R435  0R  [R0402]  35 35.69 270 top
R436  10K  [R0402]  93.51 40.64 180 top
R437  10K  [R0402]  55.26 33.66 180 top
R438  1K  [R0402]  52.72 29.72 90 top
R439  20K  [R0402]  79.07 29.65 90 top
R440  15R  [R0402]  89.8 32.26 0 top
R441  10K  [R0402]  95.88 42.42 270 top
R442  30K  [R0402]  55.26 32.64 180 top
R443  10K  [R0402]  101.61 42.35 270 top
R444  10K  [R0402]  103.77 42.29 270 top
R445  10K  [R0402]  104.79 42.29 270 top
R446  4K7  [R0402]  29.4 42.11 270 top
R447  0R  [R0402]  32.9 31.95 180 top
R448  0R  [R0402]  98.37 41.47 270 top
R449  0R  [R0402]  99.39 41.47 270 top
R450  10K  [R0402]  63.26 35.94 90 top
R451  10K  [R0402]  64.27 35.94 90 top
R452  200K  [R0402]  157.24 41.15 270 top
R453  0R  [R0402]  38.62 41.02 270 top
R454  0R  [R0402]  41.79 40.89 270 top
R455  200K  [R0402]  146.95 30.29 0 top
R456  100R  [R0402]  22.62 35.05 270 top
R457  0R  [R0402]  90.82 40.01 270 top
R458  0R  [R0402]  57.92 35.18 0 top
R459  300R  [R0603]  55 29.59 270 top
R460  300R  [R0603]  56.53 29.59 270 top
R461  300R  [R0603]  58.05 29.59 270 top
R462  4K7  [R0402]  43.44 29.72 270 top
R463  4K7  [R0402]  44.46 29.72 270 top
R464  4K7  [R0402]  45.48 29.72 270 top
R465  4K7  [R0402]  46.49 29.72 270 top
R466  1K  [R0402]  48.65 29.72 270 top
R467  10K  [R0402]  49.67 29.72 270 top
R468  10K  [R0402]  51.7 29.72 270 top
R469  0R  [R0402]  56.4 27.69 180 top
R470  499R  [R0402]  18.81 27.56 0 top
R471  0R  [R0402]  40.78 33.4 0 top
R472  0R  [R0402]  38.49 32.26 0 top
R473  0R  [R0402]  40.9 32.26 0 top
R474  0R  [R0603]  24.52 25.27 180 top
R475  1K  [R0402]  136.92 29.97 90 top
R476  47K  [R0603]  143.65 32.13 0 top
R477  0R  [R0402]  47.64 29.72 90 top
R478  0R  [R0402]  50.68 29.72 90 top
R479  10K  [R0402]  55.26 31.62 0 top
R480  0R  [R0603]  118.37 30.35 90 top
R481  1K  [R0402]  136.41 26.48 270 top
R482  1K  [R0402]  138.69 26.48 270 top
R483  4K7  [R0402]  139.84 26.48 270 top
R484  1K  [R0402]  142.12 26.48 270 top
R485  0R  [R0402]  143.27 26.48 270 top
R486  0R  [R0402]  22.17 24.07 270 top
R487  100K  [R0402]  31 25.02 270 top
R488  330R  [R0805]  64.53 28.19 90 top
R489  130R  [R0402]  115.2 19.3 90 top
R490  220R  [R0402]  113.55 22.23 180 top
R491  100K  [R0402]  146.95 29.08 180 top
R492  47K  [R0402]  137.55 26.48 90 top
R493  47K  [R0402]  140.98 26.48 90 top
R494  100K  [R0402]  72.02 28.7 180 top
R495  47K  [R0402]  144.92 27.18 0 top
R496  0R  [R0402]  33.28 25.02 90 top
R497  100K  [R0402]  72.02 27.43 180 top
R498  1K  [R0402]  76.01 26.67 0 top
R499  1K  [R0402]  53.73 29.72 270 top
R500  0R  [R0402]  56.4 26.67 180 top
R501  0R  [R0603]  27.44 25.27 0 top
R502  0R  [R0603]  61.1 18.03 270 top
R503  0R  [R0603]  62.62 18.03 270 top
R504  0R  [R0603]  64.15 18.03 270 top
R505  0R  [R0603]  84.59 18.03 270 top
R506  0R  [R0603]  86.12 18.03 270 top
R507  0R  [R0603]  87.7 18.03 270 top
R508  0R  [R0603]  89.23 18.03 270 top
R509  130R  [R0402]  113.93 19.3 90 top
R510  220R  [R0402]  114.56 17.53 180 top
R511  51K  [R0402]  72.91 14.86 90 top
R512  27K  [R0402]  72.91 10.29 270 top
R513  0R  [R0603]  59.57 18.03 270 top
R514  0R  [R0402]  42.17 9.27 270 top
R515  0R  [R0402]  43.19 9.27 270 top
R516  0R  [R0603]  39.13 9.14 90 top
R517  51K  [R0402]  51.19 10.03 180 top
R518  100K  [R0603]  153.24 16.89 270 bottom
R519  27K  [R0402]  51.19 8.89 180 top
R520  1K5  [R0805]  12.58 6.35 90 top
R521  220R  [R0402]  115.45 7.11 270 top
R522  1K  [R0402]  118.49 245.31 270 bottom
R523  1K  [R0402]  117.22 245.31 270 bottom
R524  8K2  [R0402]  83.96 231.9 270 bottom
R525  10K  [R0402]  92.19 218.59 270 bottom
R526  0R  [R0402]  84.59 216.79 270 bottom
R527  8K2  [R0402]  84.59 214.5 90 bottom
R528  0R  [R0402]  91.07 218.59 270 bottom
R529  0R  [R0805]  113.36 207.84 180 bottom
R530  0R  [R0805]  90.56 206.5 180 bottom
R531  0R  [R0603]  49.41 190.63 0 bottom
R532  2R2  [R0805]  90.12 193.55 90 bottom
R533  2R2  [R0805]  101.99 193.29 90 bottom
R534  80R6  [R0402]  114.18 177.42 90 bottom
R535  0R  [R0603]  24.9 180.21 0 bottom
R536  0R  [R0402]  22.11 174.5 0 bottom
R537  15R  [R0402]  114.77 183.97 270 bottom
R538  0R  [R0402]  22.11 173.48 0 bottom
R539  0R  [R0402]  22.11 172.47 0 bottom
R540  4K7  [R0402]  54.94 172.91 270 bottom
R541  300R  [R0402]  100.09 170.94 0 bottom
R542  0R  [R0402]  20.71 170.18 0 bottom
R543  4K7  [R0402]  60.46 172.97 90 bottom
R544  4K7  [R0402]  57.03 172.97 90 bottom
R545  4K7  [R0402]  53.92 172.91 90 bottom
R546  715R  [R0402]  59.4 170.05 270 bottom
R547  0R  [R0402]  59.22 172.47 90 bottom
R548  4K7  [R0402]  51.5 167.03 180 bottom
R549  0R  [R0402]  20.46 167.13 0 bottom
R550  0R  [R0402]  56.97 170.75 90 bottom
R551  0R  [R0402]  54.94 170.75 90 bottom
R552  0R  [R0603]  56.02 165.48 0 bottom
R553  0R  [R0402]  23.12 165.23 180 bottom
R554  0R  [R0402]  22.11 171.45 180 bottom
R555  4K7  [R0402]  52.72 169.42 90 bottom
R556  0R  [R0402]  51.45 169.42 90 bottom
R557  0R  [R0402]  65.29 172.97 270 bottom
R558  0R  [R0402]  20.46 169.16 0 bottom
R559  10K  [R0402]  10.3 161.29 180 bottom
R560  22R  [R0402]  5.73 161.29 180 bottom
R561  0R  [R0402]  20.46 168.15 0 bottom
R562  10K  [R0402]  10.3 160.02 180 bottom
R563  22R  [R0402]  5.73 160.02 180 bottom
R564  0R  [R0402]  25.54 164.59 90 bottom
R565  0R  [R0402]  23.12 166.24 180 bottom
R566  0R  [R0402]  20.46 166.12 180 bottom
R567  1K  [R0402]  157.67 144.58 0 bottom
R568  0R  [R0805]  89.29 132.08 90 bottom
R569  0R  [R0603]  68.59 134.81 270 bottom
R570  0R  [R0603]  66.56 134.81 270 bottom
R571  100R  [R0402]  64.53 138.43 180 bottom
R572  44R2  [R0402]  105.93 127.38 90 bottom
R573  0R  [R0402]  82.94 124.71 90 bottom
R574  300R  [R0402]  105.04 120.52 90 bottom
R575  300R  [R0402]  96.91 124.89 0 bottom
R576  300R  [R0402]  103.64 124.84 0 bottom
R577  300R  [R0402]  100.34 124.84 0 bottom
R578  10K  [R0402]  91.32 124.71 0 bottom
R579  5K1  [R0402]  91.32 125.73 180 bottom
R580  20K  [R0402]  84.29 124.76 270 bottom
R581  0R  [R0402]  33.79 109.09 90 bottom
R582  0R  [R0402]  32.78 109.09 90 bottom
R583  0R  [R0402]  31.13 109.09 90 bottom
R584  0R  [R0402]  30.11 109.09 90 bottom
R585  0R  [R0402]  39.13 109.03 90 bottom
R586  0R  [R0402]  38.11 109.03 90 bottom
R587  0R  [R0402]  28.9 108.65 90 bottom
R588  0R  [R0402]  27.82 108.65 90 bottom
R589  8K2  [R0402]  96.78 122.3 0 bottom
R590  0R  [R0402]  42.05 107.76 180 bottom
R591  0R  [R0402]  42.05 106.74 180 bottom
R592  10K  [R0402]  104.15 107.31 270 bottom
R593  10K  [R0402]  90.05 107.06 270 bottom
R594  10K  [R0402]  102.37 101.6 90 bottom
R595  20K5  [R0402]  105.17 111.51 0 bottom
R596  261R  [R0402]  38.62 110.55 180 bottom
R597  20K  [R0402]  110.88 103.5 180 bottom
R598  10K  [R0402]  108.47 106.81 90 bottom
R599  300R  [R0402]  62.14 101.63 90 bottom
R600  33R  [R0402]  40.84 93.6 90 bottom
R601  158R  [R0402]  42.43 95.76 180 bottom
R602  0R  [R0402]  81.42 91.69 0 bottom
R603  0R  [R0603]  19.81 94.92 180 bottom
R604  0R  [R0603]  19.81 93.27 180 bottom
R605  8K2  [R0402]  39.7 93.6 90 bottom
R606  8K2  [R0402]  38.68 93.6 90 bottom
R607  0R  [R0402]  34.62 93.6 90 bottom
R608  0R  [R0402]  33.6 93.6 90 bottom
R609  90R9  [R0402]  42.43 94.74 180 bottom
R610  10K  [R0402]  79.13 91.69 180 bottom
R611  1K  [R0402]  35.32 85.34 0 bottom
R612  10K  [R0402]  84.59 86.23 270 bottom
R613  10K  [R0402]  82.31 86.11 270 bottom
R614  22R  [R0402]  37.67 93.6 270 bottom
R615  22R  [R0402]  36.65 93.6 270 bottom
R616  33R  [R0402]  35.63 93.6 270 bottom
R617  0R  [R0402]  32.46 93.6 270 bottom
R618  0R  [R0402]  31.44 93.6 270 bottom
R619  0R  [R0402]  30.3 93.6 270 bottom
R620  0R  [R0402]  29.28 93.6 270 bottom
R621  0R  [R0402]  28.14 93.6 270 bottom
R622  0R  [R0402]  27.13 93.6 270 bottom
R623  0R  [R0402]  25.98 93.6 270 bottom
R624  0R  [R0402]  24.97 93.6 270 bottom
R625  0R  [R0603]  19.31 88.19 90 bottom
R626  0R  [R0603]  17.78 88.19 90 bottom
R627  10K  [R0402]  26.93 79.5 90 bottom
R628  10K  [R0402]  50.43 78.74 90 bottom
R629  0R  [R0402]  35.19 78.61 90 bottom
R630  10K  [R0402]  85.69 86.23 90 bottom
R631  10K  [R0402]  83.45 86.23 90 bottom
R632  100K  [R0402]  35.32 88.14 0 bottom
R633  0R  [R0402]  33.79 84.71 90 bottom
R634  10K  [R0402]  35.32 87 0 bottom
R635  10K  [R0402]  86.02 83.06 90 bottom
R636  22R  [R0402]  84.72 83.06 90 bottom
R637  22R  [R0402]  83.45 83.06 90 bottom
R638  0R  [R0402]  32.71 87.44 270 bottom
R639  0R  [R0402]  31.7 87.44 270 bottom
R640  0R  [R0402]  41.79 87.38 270 bottom
R641  0R  [R0402]  40.52 87.38 270 bottom
R642  2K2  [R0402]  111.64 77.47 0 bottom
R643  0R  [R0402]  81.16 76.71 180 bottom
R644  100K  [R0603]  158.25 81.72 90 bottom
R645  27K  [R0402]  17.92 75.95 180 bottom
R646  2K2  [R0402]  111.64 76.33 0 bottom
R647  0R  [R0603]  109.17 77.03 270 bottom
R648  0R  [R0402]  29.92 85.03 270 bottom
R649  10K  [R0402]  109.55 74.8 0 bottom
R650  0R  [R0402]  31.95 84.52 270 bottom
R651  0R  [R0402]  30.94 84.52 270 bottom
R652  0R  [R0402]  51.45 78.74 90 bottom
R653  4K7  [R0402]  115.45 73.03 0 bottom
R654  10K  [R0402]  82.81 77.22 90 bottom
R655  10K  [R0402]  109.55 72.45 0 bottom
R656  8K2  [R0402]  106.44 71.37 0 bottom
R657  0R  [R0603]  84.85 75.82 90 bottom
R658  0R  [R0402]  50.56 77.09 180 bottom
R659  100K  [R0402]  28.08 79.5 270 bottom
R660  0R  [R0402]  112.53 74.23 180 bottom
R661  75R  [R0402]  17.41 64.26 90 bottom
R662  0R  [R0402]  109.55 73.79 180 bottom
R663  51K  [R0402]  17.66 74.04 270 bottom
R664  1K  [R0402]  100.59 64.85 270 bottom
R665  0R  [R0603]  93.86 67.94 90 bottom
